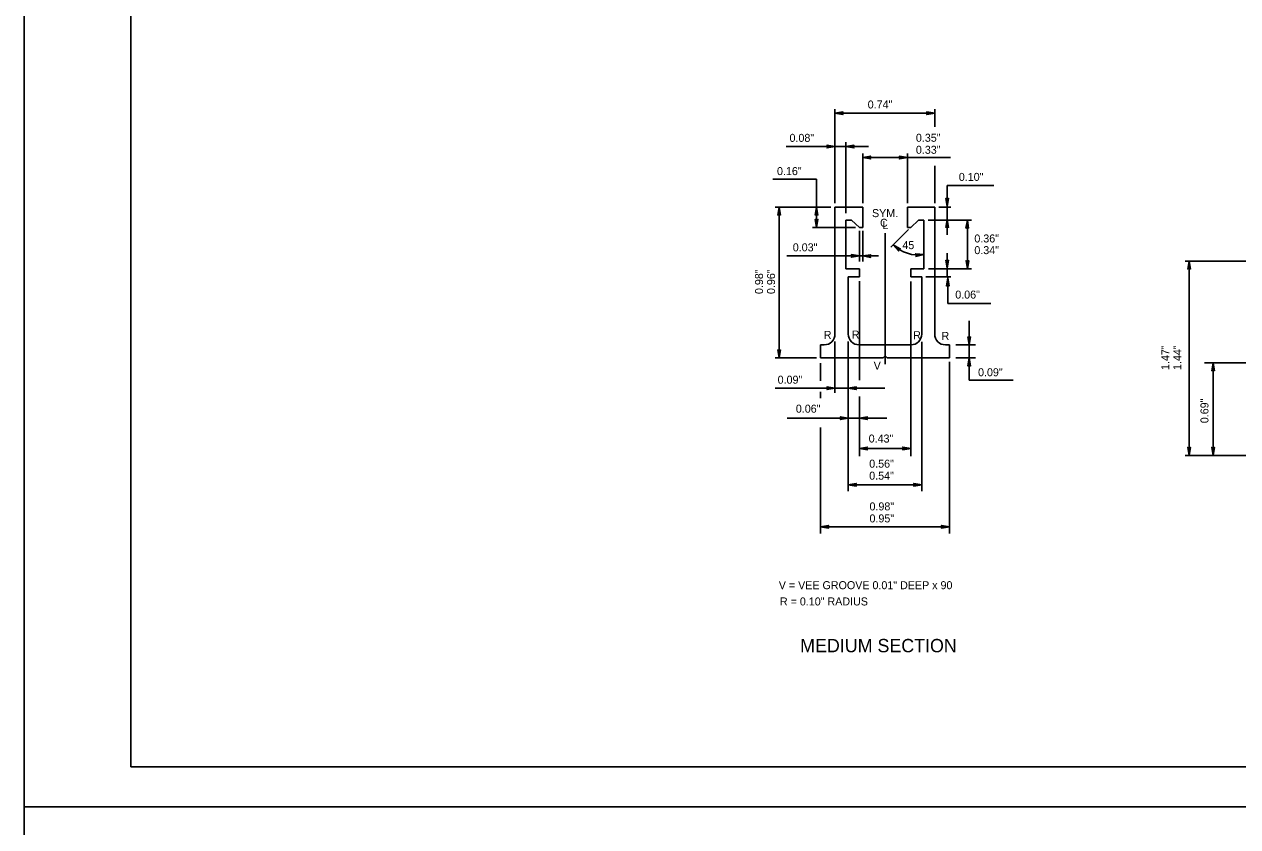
# Model space of a CAD drawing. Extents: x 650495 to 652241, y 298458 to 299646.
# Drawn here: x 650495.3 to 650950.2, y 299044.1 to 299344.9 of the extents above; entities that cross this region are included whole.
import ezdxf

# ---------------------------------------------------------------- set-up
doc = ezdxf.new("R2010")
doc.units = 0
for name, color, linetype in [('1', 7, 'Continuous'), ('2', 7, 'Continuous'), ('3', 7, 'Continuous'), ('PLT-BNDY', 7, 'Continuous')]:
    doc.layers.add(name, color=color, linetype=linetype)

# ---------------------------------------------------------------- blocks, each defined once
blk = doc.blocks.new('RARROW')
at = {"layer": '3'}
blk.add_lwpolyline([(-2.2695, 0.285), (-2.184875, 0.12075), (0, 0), (-2.2695, 0.285), (-2.38575, 0.384625), (0, 0), (-2.183125, -0.108), (-2.262875, -0.2705), (0, 0), (-2.38575, -0.379125), (-2.262875, -0.2705)], dxfattribs=at)

msp = doc.modelspace()

# ---------------------------------------------------------------- linework, layer by layer
at = {"layer": '1'}
for p, q in [((650535.31, 299630.63), (650535.31, 299066.63)), ((651321.31, 299066.63), (650535.31, 299066.63)), ((650535.31, 299066.63), (651121.31, 299066.63))]:
    msp.add_line(p, q, dxfattribs=at)
at = {"layer": '2'}
for p, q in [((650799.19, 299277.85), (650799.19, 299313.05)), ((650836.57, 299306.49), (650836.57, 299313.05)), ((650799.19, 299311.55), (650836.57, 299311.55)), ((650799.19, 299299.03), (650780.85, 299299.03)), ((650811.8, 299299.03), (650799.19, 299299.03)), ((650803.27, 299300.72), (650803.27, 299274.07)), ((650809.57, 299277.85), (650809.57, 299296.41)), ((650842.46, 299294.91), (650809.57, 299294.91)), ((650826.32, 299277.85), (650826.32, 299296.41)), ((650836.57, 299277.85), (650836.57, 299291.85)), ((650792.32, 299286.85), (650775.88, 299286.85)), ((650792.32, 299286.85), (650792.32, 299268.73)), ((650841.26, 299284.47), (650841.26, 299276.59)), ((650841.26, 299284.47), (650858.76, 299284.47)), ((650797.69, 299276.35), (650776.74, 299276.35)), ((650778.24, 299276.35), (650778.24, 299219.85)), ((650799.19, 299276.35), (650809.57, 299276.35)), ((650799.19, 299276.35), (650799.19, 299228.73)), ((650809.57, 299276.35), (650809.57, 299268.73)), ((650809.57, 299276.35), (650809.57, 299276.35)), ((650836.57, 299276.35), (650826.32, 299276.35)), ((650826.32, 299276.35), (650826.32, 299268.73)), ((650826.32, 299276.35), (650826.32, 299276.35)), ((650836.57, 299228.73), (650836.57, 299276.35)), ((650838.07, 299276.35), (650842.63, 299276.35)), ((650841.26, 299276.59), (650841.26, 299265.99)), ((650806.82, 299268.73), (650790.82, 299268.73)), ((650805.44, 299271.48), (650803.27, 299271.48)), ((650803.27, 299271.48), (650803.27, 299253.23)), ((650805.44, 299271.48), (650808.32, 299268.73)), ((650809.57, 299268.73), (650808.32, 299268.73)), ((650808.32, 299255.93), (650808.32, 299267.43)), ((650809.57, 299255.93), (650809.57, 299267.43)), ((650826.74, 299267.94), (650820.15, 299261.36)), ((650826.32, 299268.73), (650827.57, 299268.73)), ((650830.44, 299271.48), (650827.57, 299268.73)), ((650830.44, 299271.48), (650832.49, 299271.48)), ((650832.49, 299271.48), (650832.49, 299253.23)), ((650834.15, 299271.48), (650850.3, 299271.48)), ((650848.8, 299253.23), (650848.8, 299271.48)), ((650817.94, 299217.44), (650817.94, 299266.58)), ((650781.14, 299258.03), (650808.32, 299258.03)), ((650808.32, 299258.03), (650815.56, 299258.03)), ((650841.26, 299259.04), (650841.26, 299250.46)), ((650980.03, 299256.15), (650930.42, 299256.15)), ((650931.92, 299256.15), (650931.92, 299183.27)), ((650803.27, 299253.23), (650808.32, 299253.23)), ((650804.19, 299228.73), (650804.19, 299250.23)), ((650804.19, 299250.23), (650808.32, 299250.23)), ((650808.32, 299253.23), (650808.32, 299250.23)), ((650832.49, 299253.23), (650827.57, 299253.23)), ((650827.57, 299253.23), (650827.57, 299250.23)), ((650827.57, 299250.23), (650831.69, 299250.23)), ((650831.69, 299250.23), (650831.69, 299228.73)), ((650833.19, 299250.23), (650842.63, 299250.23)), ((650834.26, 299253.23), (650850.3, 299253.23)), ((650841.44, 299249.8), (650841.44, 299240.21)), ((650808.32, 299248.62), (650808.32, 299211.44)), ((650827.57, 299183), (650827.57, 299248.44)), ((650841.44, 299240.21), (650857.66, 299240.21)), ((650849.5, 299219.85), (650849.5, 299233.78)), ((650795.19, 299224.73), (650793.82, 299224.73)), ((650793.82, 299224.73), (650793.82, 299219.85)), ((650799.19, 299225.98), (650799.19, 299206.72)), ((650804.19, 299225.98), (650804.19, 299169.88)), ((650827.69, 299224.73), (650808.19, 299224.73)), ((650831.69, 299225.88), (650831.69, 299169.88)), ((650842.07, 299224.73), (650840.57, 299224.73)), ((650842.07, 299219.85), (650842.07, 299224.73)), ((650851.84, 299224.73), (650844.54, 299224.73)), ((650792.32, 299219.85), (650776.74, 299219.85)), ((650793.82, 299219.85), (650817.19, 299219.85)), ((650793.82, 299217.85), (650793.82, 299211.21)), ((650818.69, 299219.85), (650842.07, 299219.85)), ((650842.07, 299218.35), (650842.07, 299153.99)), ((650844.54, 299219.85), (650851.84, 299219.85)), ((650849.5, 299211.53), (650849.5, 299219.85)), ((650963.28, 299218.03), (650937.68, 299218.03)), ((650940.92, 299218.03), (650940.92, 299183.27)), ((650799.19, 299208.48), (650776.71, 299208.48)), ((650817.87, 299208.48), (650799.19, 299208.48)), ((650849.5, 299211.53), (650865.95, 299211.53)), ((650793.82, 299207.17), (650793.82, 299204.7)), ((650808.32, 299205.38), (650808.32, 299183)), ((650781.32, 299197.23), (650804.19, 299197.23)), ((650818.6, 299197.23), (650804.19, 299197.23)), ((650793.82, 299193.77), (650793.82, 299153.99)), ((650827.57, 299185.91), (650808.32, 299185.91)), ((650963.28, 299183.27), (650930.42, 299183.27)), ((650804.19, 299172.3), (650831.69, 299172.3)), ((650793.82, 299156.53), (650842.07, 299156.53))]:
    msp.add_line(p, q, dxfattribs=at)
msp.add_lwpolyline([(650817.19, 299219.85), (650817.94, 299220.6), (650818.69, 299219.85)], dxfattribs=at)
for centre, radius, start, end in [((650830.27, 299271.48), 13.06, 225.0095, 279.8021), ((650795.19, 299228.73), 4, 270, 0), ((650808.19, 299228.73), 4, 180, 270), ((650827.69, 299228.73), 4, 270, 0), ((650840.57, 299228.73), 4, 180, 270)]:
    msp.add_arc(centre, radius, start, end, dxfattribs=at)
at = {"layer": 'PLT-BNDY'}
for points in [[(650495.31, 299645.63), (651336.31, 299645.63), (651336.31, 299051.63), (650495.31, 299051.63)], [(650495.31, 299051.63), (651336.31, 299051.63), (651336.31, 298457.63), (650495.31, 298457.63)]]:
    msp.add_lwpolyline(points, close=True, dxfattribs=at)

# ---------------------------------------------------------------- block references
at = {"layer": '2', "xscale": 1.2574347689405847}
for p, yscale, rotation in [((650799.19, 299311.55), 1.3092961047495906, 180), ((650803.27, 299299.03), 1.3092961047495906, 180), ((650809.57, 299294.91), 1.3092961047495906, 180), ((650778.24, 299276.35), 1.3092961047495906, 89.99999999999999), ((650792.32, 299276.35), 1.3092961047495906, 89.99999999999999), ((650841.26, 299276.59), 1.3092961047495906, -90.00000000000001), ((650792.32, 299268.73), 1.3092961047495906, -90.00000000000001), ((650841.26, 299271.71), 1.3092961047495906, 89.99999999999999), ((650848.8, 299271.48), 1.3092961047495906, 89.99999999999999), ((650821.04, 299262.24), 1.3092961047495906, 140.9194989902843), ((650809.57, 299258.03), 1.3092961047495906, 180), ((650832.49, 299258.61), 1.3092961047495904, 4.175089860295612), ((650841.26, 299253.46), 1.3092961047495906, -90.00000000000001), ((650848.8, 299253.23), 1.3092961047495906, -90.00000000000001), ((650931.92, 299256.15), 1.3092961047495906, 89.99999999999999), ((650841.44, 299249.8), 1.3092961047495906, 89.99999999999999), ((650849.5, 299224.73), 1.3092961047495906, -90.00000000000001), ((650778.24, 299219.85), 1.3092961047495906, -90.00000000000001), ((650849.5, 299219.85), 1.3092961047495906, 89.99999999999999), ((650940.92, 299218.03), 1.3092961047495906, 89.99999999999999), ((650804.19, 299208.48), 1.3092961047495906, 180), ((650808.32, 299197.23), 1.3092961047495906, 180), ((650808.32, 299185.91), 1.3092961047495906, 180), ((650931.92, 299183.27), 1.3092961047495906, -90.00000000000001), ((650940.92, 299183.27), 1.3092961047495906, -90.00000000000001), ((650804.19, 299172.3), 1.3092961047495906, 180), ((650793.82, 299156.53), 1.3092961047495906, 180)]:
    msp.add_blockref('RARROW', p, dxfattribs=dict(at, yscale=yscale, rotation=rotation))
at = {"layer": '2', "xscale": 1.2574347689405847, "yscale": 1.3092961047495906}
for p in [(650836.57, 299311.55), (650799.19, 299299.03), (650826.32, 299294.91), (650808.32, 299258.03), (650799.19, 299208.48), (650804.19, 299197.23), (650827.57, 299185.91), (650831.69, 299172.3), (650842.07, 299156.53)]:
    msp.add_blockref('RARROW', p, dxfattribs=at)

# ---------------------------------------------------------------- texts
at = {"layer": '2'}
for s, height, p in [('0.74"', 3, (650811.46, 299313.32)), ('0.08"', 3, (650782.15, 299300.8)), ('0.35"', 3, (650829.52, 299300.84)), ('0.33"', 3, (650829.52, 299296.34)), ('0.16"', 3, (650777.46, 299288.35)), ('0.10"', 3, (650845.61, 299286.17)), ('SYM.', 3, (650813.07, 299272.6)), ('C', 3, (650816.07, 299268.98)), ('L', 3, (650816.94, 299268.1)), ('0.03"', 3, (650783.37, 299259.77)), ('45', 3, (650824.45, 299260.61)), ('0.36"', 3, (650851.43, 299263.1)), ('0.34"', 3, (650851.43, 299258.73)), ('0.06"', 3, (650844.28, 299242.06)), ('R', 3, (650794.97, 299226.98)), ('R', 3, (650805.47, 299227.1)), ('R', 3, (650828.5, 299226.85)), ('R', 3, (650839.14, 299226.57)), ('V', 3, (650813.69, 299215.43)), ('0.09"', 3, (650777.7, 299210.16)), ('0.09"', 3, (650852.82, 299212.96)), ('0.06"', 3, (650784.52, 299199.3)), ('0.43"', 3, (650811.82, 299188.11)), ('0.56"', 3, (650812.03, 299178.69)), ('0.54"', 3, (650812.03, 299174.19)), ('0.98"', 3, (650812.13, 299162.68)), ('0.95"', 3, (650812.13, 299158.18)), ('V = VEE GROOVE 0.01" DEEP x 90', 3, (650778.13, 299133.15)), ('R = 0.10" RADIUS', 3, (650778.56, 299127.06)), ('MEDIUM SECTION', 5, (650786.15, 299109.51))]:
    msp.add_text(s, height=height, dxfattribs=at).set_placement(p)
for s, p in [('0.98"', (650772.22, 299243.78)), ('0.96"', (650776.72, 299243.78)), ('1.47"', (650924.51, 299215.3)), ('1.44"', (650929.01, 299215.3)), ('0.69"', (650939.18, 299195.36))]:
    msp.add_text(s, height=3, rotation=90, dxfattribs=at).set_placement(p)

doc.saveas('drawing.dxf')
